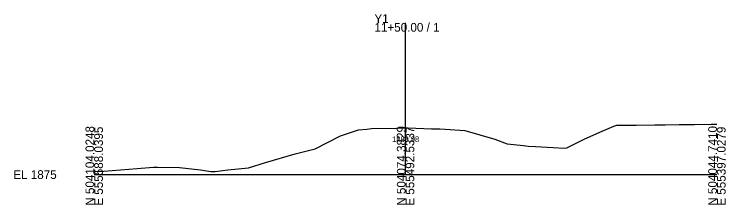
# Model space of a CAD drawing. Extents: x -26 to 1503, y -10 to 5015.
# Drawn here: x -25.7 to 202.8, y 1490.3 to 1551.5 of the extents above; entities that cross this region are included whole.
import ezdxf

# ---------------------------------------------------------------- set-up
doc = ezdxf.new("R2010")
doc.units = 0
for name, color, linetype in [('Default', 7, 'Continuous'), ('Exist Cross Section Cell', 7, 'Continuous'), ('Exist XS Center Line Elevation Label', 7, 'Continuous'), ('Exist XS Ground Line', 7, 'Continuous')]:
    doc.layers.add(name, color=color, linetype=linetype)

msp = doc.modelspace()

# ---------------------------------------------------------------- linework, layer by layer
at = {"layer": 'Exist Cross Section Cell'}
for p, q in [((100, 1500), (100, 1548.71)), ((0, 1500), (100, 1500)), ((100, 1500), (200, 1500))]:
    msp.add_line(p, q, dxfattribs=at)
at = {"layer": 'Exist XS Ground Line'}
for p, q in [((163.14, 1513.95), (166.91, 1515.54)), ((166.91, 1515.54), (167.86, 1515.83)), ((167.86, 1515.83), (172.5, 1515.87)), ((172.5, 1515.87), (174.06, 1515.87)), ((174.06, 1515.87), (180.04, 1515.96)), ((180.04, 1515.96), (183.37, 1516)), ((183.37, 1516), (187.85, 1516.06)), ((187.85, 1516.06), (192.85, 1516.13)), ((192.85, 1516.13), (198.16, 1516.21)), ((198.16, 1516.21), (200, 1516.24)), ((79.79, 1512.65), (84.85, 1514.42)), ((84.85, 1514.42), (87.59, 1514.62)), ((87.59, 1514.62), (89.1, 1514.76)), ((89.1, 1514.76), (97.11, 1514.93)), ((97.11, 1514.93), (100, 1514.98)), ((100, 1514.98), (100.87, 1514.99)), ((100.87, 1514.99), (108.28, 1514.75)), ((108.28, 1514.75), (110.95, 1514.66)), ((110.95, 1514.66), (112.71, 1514.54)), ((112.71, 1514.54), (119.02, 1514.14)), ((119.02, 1514.14), (128.7, 1511.33)), ((157.59, 1511.45), (163.14, 1513.95)), ((70.95, 1508.3), (79.13, 1512.44)), ((79.13, 1512.44), (79.79, 1512.65)), ((128.7, 1511.33), (132.59, 1509.93)), ((151.78, 1508.6), (157.59, 1511.45)), ((132.59, 1509.93), (137.92, 1509.3)), ((137.92, 1509.3), (139.37, 1509.12)), ((139.37, 1509.12), (141.71, 1509.05)), ((141.71, 1509.05), (147.37, 1508.73)), ((147.37, 1508.73), (150.98, 1508.52)), ((150.98, 1508.52), (151.78, 1508.6)), ((54.97, 1503.87), (64.56, 1506.66)), ((64.56, 1506.66), (70.95, 1508.3)), ((49.55, 1502.17), (54.97, 1503.87)), ((3.11, 1501.06), (13.77, 1501.97)), ((13.77, 1501.97), (19.03, 1502.39)), ((19.03, 1502.39), (20.3, 1502.4)), ((20.3, 1502.4), (27.39, 1502.3)), ((27.39, 1502.3), (34.16, 1501.54)), ((34.16, 1501.54), (37.43, 1501.04)), ((41.29, 1501.31), (42.9, 1501.54)), ((42.9, 1501.54), (49.55, 1502.17)), ((0, 1501.04), (3.11, 1501.06)), ((37.43, 1501.04), (38.8, 1500.99)), ((38.8, 1500.99), (41.29, 1501.31))]:
    msp.add_line(p, q, dxfattribs=at)

# ---------------------------------------------------------------- texts
at = {"layer": 'Default'}
msp.add_text('-', height=0.0001, dxfattribs=at).set_placement((0, 1500))
at = {"layer": 'Exist Cross Section Cell'}
for s, p in [('Y1', (90, 1548.71)), ('11+50.00 / 1', (90, 1545.91)), ('EL 1875', (-26, 1498.6))]:
    msp.add_text(s, height=2.8, dxfattribs=at).set_placement(p)
for s, p in [('N 504104.0248', (0, 1490)), ('E 555588.0395', (2.8, 1490)), ('N 504074.3829', (100, 1490)), ('E 555492.5337', (102.8, 1490)), ('N 504044.7410', (200, 1490)), ('E 555397.0279', (202.8, 1490))]:
    msp.add_text(s, height=2.8, rotation=90, dxfattribs=at).set_placement(p)
at = {"layer": 'Exist XS Center Line Elevation Label'}
msp.add_text('1889.98', height=1.8, dxfattribs=at).set_placement((95.66, 1510.45))

doc.saveas('drawing.dxf')
